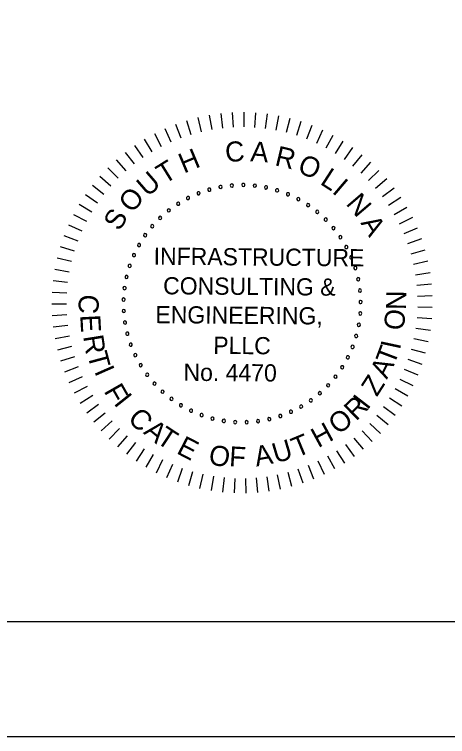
# Model space of a CAD drawing. Extents: x -146.3 to -98.2, y -113.4 to -84.1.
# Drawn here: x -112.521 to -110.009, y -113.391 to -109.207 of the extents above; entities that cross this region are included whole.
import ezdxf

# ---------------------------------------------------------------- set-up
doc = ezdxf.new("R2010")
doc.units = 0
for name, color, linetype in [('BR_BORDER LINES', 7, 'Continuous'), ('BR_TEXT', 7, 'Continuous'), ('Level 31', 7, 'Continuous')]:
    doc.layers.add(name, color=color, linetype=linetype)

msp = doc.modelspace()

# ---------------------------------------------------------------- linework, layer by layer
at = {"layer": 'BR_BORDER LINES'}
msp.add_line((-143.8657, -112.7249), (-98.9787, -112.7249), dxfattribs=at)
at = {"layer": 'BR_TEXT'}
for p, q in [((-111.4572, -109.8039), (-111.4373, -109.8864)), ((-111.3912, -109.7902), (-111.3765, -109.8738)), ((-111.3246, -109.7806), (-111.315, -109.865)), ((-111.2575, -109.7751), (-111.2531, -109.8599)), ((-111.1902, -109.7737), (-111.1909, -109.8586)), ((-111.123, -109.7764), (-111.1289, -109.8611)), ((-111.056, -109.7832), (-111.067, -109.8674)), ((-110.9896, -109.794), (-111.0057, -109.8774)), ((-111.5859, -109.8431), (-111.5562, -109.9226)), ((-111.5221, -109.8215), (-111.4973, -109.9027)), ((-110.9239, -109.8089), (-110.9451, -109.8911)), ((-110.8593, -109.8278), (-110.8855, -109.9085)), ((-111.6482, -109.8685), (-111.6137, -109.946)), ((-110.796, -109.8505), (-110.827, -109.9296)), ((-110.7341, -109.8771), (-110.7699, -109.9541)), ((-111.7089, -109.8976), (-111.6697, -109.9729)), ((-110.674, -109.9074), (-110.7145, -109.9821)), ((-111.8243, -109.9667), (-111.7763, -110.0367)), ((-111.7677, -109.9304), (-111.724, -110.0032)), ((-110.6159, -109.9413), (-110.6608, -110.0134)), ((-111.8787, -110.0065), (-111.8264, -110.0734)), ((-110.5599, -109.9787), (-110.6091, -110.0479)), ((-111.9305, -110.0494), (-111.8743, -110.113)), ((-110.5063, -110.0195), (-110.5597, -110.0855)), ((-111.9796, -110.0954), (-111.9196, -110.1555)), ((-110.4553, -110.0634), (-110.5126, -110.1261)), ((-110.4071, -110.1103), (-110.4681, -110.1694)), ((-112.0258, -110.1444), (-111.9623, -110.2007)), ((-110.3618, -110.1602), (-110.4263, -110.2154)), ((-112.069, -110.196), (-112.0021, -110.2484)), ((-110.3197, -110.2126), (-110.3874, -110.2638)), ((-112.1089, -110.2502), (-112.039, -110.2984)), ((-110.2808, -110.2676), (-110.3515, -110.3146)), ((-112.1454, -110.3068), (-112.0727, -110.3506)), ((-110.2454, -110.3248), (-110.3188, -110.3674)), ((-112.1784, -110.3654), (-112.1032, -110.4047)), ((-110.2134, -110.3841), (-110.2893, -110.4221)), ((-112.2078, -110.426), (-112.1303, -110.4606)), ((-110.1852, -110.4452), (-110.2633, -110.4785)), ((-112.2334, -110.4882), (-112.154, -110.5181)), ((-110.1608, -110.5079), (-110.2407, -110.5364)), ((-112.2552, -110.5519), (-112.1741, -110.5768)), ((-110.1402, -110.572), (-110.2217, -110.5955)), ((-112.2731, -110.6168), (-112.1906, -110.6367)), ((-110.1235, -110.6372), (-110.2064, -110.6557)), ((-112.287, -110.6827), (-112.2034, -110.6975)), ((-110.1109, -110.7033), (-110.1947, -110.7168)), ((-112.2968, -110.7493), (-112.2125, -110.759)), ((-110.1023, -110.7701), (-110.1868, -110.7784)), ((-112.3026, -110.8163), (-112.2178, -110.8209)), ((-110.0978, -110.8372), (-110.1827, -110.8404)), ((-112.3043, -110.8836), (-112.2194, -110.883)), ((-110.0975, -110.9045), (-110.1823, -110.9025)), ((-112.3018, -110.9509), (-112.2171, -110.9451)), ((-110.1012, -110.9717), (-110.1858, -110.9646)), ((-112.2953, -111.0179), (-112.2111, -111.0069)), ((-110.109, -111.0386), (-110.193, -111.0263)), ((-112.2847, -111.0843), (-112.2013, -111.0683)), ((-110.1208, -111.1048), (-110.2039, -111.0874)), ((-112.27, -111.15), (-112.1878, -111.1289)), ((-110.1367, -111.1703), (-110.2186, -111.1478)), ((-112.2514, -111.2147), (-112.1706, -111.1887)), ((-110.1566, -111.2346), (-110.2369, -111.2072)), ((-112.2289, -111.2781), (-112.1498, -111.2472)), ((-110.1803, -111.2976), (-110.2588, -111.2653)), ((-112.2025, -111.3401), (-112.1255, -111.3044)), ((-110.2078, -111.359), (-110.2842, -111.322)), ((-112.1725, -111.4003), (-112.0978, -111.36)), ((-110.239, -111.4186), (-110.3131, -111.3771)), ((-112.1388, -111.4586), (-112.0667, -111.4138)), ((-110.2738, -111.4762), (-110.3452, -111.4303)), ((-112.1016, -111.5147), (-112.0323, -111.4656)), ((-112.061, -111.5684), (-111.9949, -111.5152)), ((-110.3121, -111.5316), (-110.3805, -111.4814)), ((-110.3536, -111.5846), (-110.4188, -111.5303)), ((-112.0173, -111.6196), (-111.9546, -111.5624)), ((-110.3983, -111.6349), (-110.4601, -111.5767)), ((-111.9705, -111.668), (-111.9114, -111.6071)), ((-110.446, -111.6824), (-110.5041, -111.6206)), ((-111.9209, -111.7134), (-111.8656, -111.649)), ((-110.4965, -111.7269), (-110.5507, -111.6616)), ((-111.8686, -111.7558), (-111.8173, -111.6881)), ((-111.8138, -111.7949), (-111.7667, -111.7242)), ((-110.5496, -111.7683), (-110.5998, -111.6998)), ((-111.7567, -111.8305), (-111.714, -111.7571)), ((-110.6629, -111.8409), (-110.7043, -111.7668)), ((-110.6051, -111.8063), (-110.651, -111.7349)), ((-111.6975, -111.8627), (-111.6594, -111.7868)), ((-110.7226, -111.8719), (-110.7595, -111.7954)), ((-111.6365, -111.8911), (-111.6031, -111.8131)), ((-111.5739, -111.9158), (-111.5453, -111.8359)), ((-110.8472, -111.9227), (-110.8745, -111.8423)), ((-110.7842, -111.8992), (-110.8163, -111.8206)), ((-111.5099, -111.9366), (-111.4862, -111.8551)), ((-111.4447, -111.9535), (-111.4261, -111.8707)), ((-111.3787, -111.9664), (-111.3651, -111.8826)), ((-111.312, -111.9752), (-111.3035, -111.8907)), ((-111.2448, -111.9799), (-111.2415, -111.8951)), ((-111.1775, -111.9806), (-111.1794, -111.8957)), ((-111.1103, -111.9771), (-111.1173, -111.8925)), ((-111.0434, -111.9695), (-111.0556, -111.8855)), ((-110.9771, -111.9579), (-110.9944, -111.8748)), ((-110.9116, -111.9423), (-110.934, -111.8604))]:
    msp.add_line(p, q, dxfattribs=at)
for centre, start, end in [((-111.3904, -110.2219), 16.1422, 196.1422), ((-111.3904, -110.2219), 196.1422, 16.1422), ((-111.3257, -110.2067), 10.6038, 190.6038), ((-111.3257, -110.2067), 190.6038, 10.6038), ((-111.2599, -110.1978), 5.0653, 185.0653), ((-111.2599, -110.1978), 185.0653, 5.0653), ((-111.1935, -110.1952), 359.5268, 179.5268), ((-111.1935, -110.1952), 179.5268, 359.5268), ((-111.1272, -110.1991), 353.9884, 173.9884), ((-111.1272, -110.1991), 173.9884, 353.9884), ((-111.0615, -110.2094), 168.4499, 348.4499), ((-111.0615, -110.2094), 348.4499, 168.4499), ((-110.9972, -110.226), 342.9114, 162.9114), ((-111.5138, -110.2707), 27.2191, 207.2191), ((-111.4533, -110.2433), 21.6807, 201.6807), ((-111.4533, -110.2433), 201.6807, 21.6807), ((-110.9972, -110.226), 162.9114, 342.9114), ((-110.9347, -110.2486), 157.373, 337.373), ((-110.9347, -110.2486), 337.373, 157.373), ((-111.5714, -110.3038), 32.7576, 212.7576), ((-111.5714, -110.3038), 212.7576, 32.7576), ((-111.5138, -110.2707), 207.2191, 27.2191), ((-110.8748, -110.2773), 151.8345, 331.8345), ((-110.8748, -110.2773), 331.8345, 151.8345), ((-110.8178, -110.3115), 146.2961, 326.2961), ((-110.8178, -110.3115), 326.2961, 146.2961), ((-111.6256, -110.3423), 38.2961, 218.2961), ((-111.6256, -110.3423), 218.2961, 38.2961), ((-110.7645, -110.3511), 140.7576, 320.7576), ((-110.7645, -110.3511), 320.7576, 140.7576), ((-111.6757, -110.3859), 43.8345, 223.8345), ((-111.6757, -110.3859), 223.8345, 43.8345), ((-110.7152, -110.3957), 135.2191, 315.2191), ((-110.7152, -110.3957), 315.2191, 135.2191), ((-111.7215, -110.434), 49.373, 229.373), ((-111.7215, -110.434), 229.373, 49.373), ((-110.6705, -110.4448), 129.6807, 309.6807), ((-110.6705, -110.4448), 309.6807, 129.6807), ((-111.7624, -110.4864), 54.9114, 234.9114), ((-111.7624, -110.4864), 234.9114, 54.9114), ((-110.6307, -110.498), 124.1422, 304.1422), ((-110.6307, -110.498), 304.1422, 124.1422), ((-111.798, -110.5425), 60.4499, 240.4499), ((-111.798, -110.5425), 240.4499, 60.4499), ((-110.5962, -110.5548), 118.6038, 298.6038), ((-110.5962, -110.5548), 298.6038, 118.6038), ((-111.8281, -110.6017), 65.9884, 245.9884), ((-111.8281, -110.6017), 245.9884, 65.9884), ((-110.5674, -110.6147), 113.0653, 293.0653), ((-110.5674, -110.6147), 293.0653, 113.0653), ((-111.8522, -110.6636), 71.5268, 251.5268), ((-111.8522, -110.6636), 251.5268, 71.5268), ((-110.5444, -110.677), 107.5268, 287.5268), ((-110.5444, -110.677), 287.5268, 107.5268), ((-111.8704, -110.7275), 77.0653, 257.0653), ((-111.8704, -110.7275), 257.0653, 77.0653), ((-110.5277, -110.7413), 101.9884, 281.9884), ((-110.5277, -110.7413), 281.9884, 101.9884), ((-111.8822, -110.7929), 82.6038, 262.6038), ((-111.8822, -110.7929), 262.6038, 82.6038), ((-110.5171, -110.8069), 96.4499, 276.4499), ((-110.5171, -110.8069), 276.4499, 96.4499), ((-111.8877, -110.8591), 88.1422, 268.1422), ((-111.8877, -110.8591), 268.1422, 88.1422), ((-110.513, -110.8732), 90.9114, 270.9114), ((-110.513, -110.8732), 270.9114, 90.9114), ((-111.8868, -110.9256), 93.6807, 273.6807), ((-111.8868, -110.9256), 273.6807, 93.6807), ((-110.5153, -110.9396), 85.373, 265.373), ((-110.5153, -110.9396), 265.373, 85.373), ((-111.8794, -110.9916), 99.2191, 279.2191), ((-111.8794, -110.9916), 279.2191, 99.2191), ((-110.524, -111.0055), 79.8345, 259.8345), ((-110.524, -111.0055), 259.8345, 79.8345), ((-111.8658, -111.0566), 104.7576, 284.7576), ((-111.8658, -111.0566), 284.7576, 104.7576), ((-110.539, -111.0702), 74.2961, 254.2961), ((-110.539, -111.0702), 254.2961, 74.2961), ((-111.8459, -111.12), 110.2961, 290.2961), ((-111.8459, -111.12), 290.2961, 110.2961), ((-110.5601, -111.1332), 68.7576, 248.7576), ((-110.5601, -111.1332), 248.7576, 68.7576), ((-111.82, -111.1812), 115.8345, 295.8345), ((-111.82, -111.1812), 295.8345, 115.8345), ((-110.5873, -111.1938), 63.2191, 243.2191), ((-110.5873, -111.1938), 243.2191, 63.2191), ((-111.7883, -111.2396), 121.373, 301.373), ((-111.7883, -111.2396), 301.373, 121.373), ((-110.6202, -111.2515), 57.6807, 237.6807), ((-110.6202, -111.2515), 237.6807, 57.6807), ((-111.7511, -111.2946), 126.9114, 306.9114), ((-111.7511, -111.2946), 306.9114, 126.9114), ((-110.6585, -111.3058), 52.1422, 232.1422), ((-110.6585, -111.3058), 232.1422, 52.1422), ((-111.7088, -111.3459), 132.4499, 312.4499), ((-111.7088, -111.3459), 312.4499, 132.4499), ((-110.7018, -111.3562), 46.6038, 226.6038), ((-110.7018, -111.3562), 226.6038, 46.6038), ((-111.6617, -111.3927), 137.9884, 317.9884), ((-111.6617, -111.3927), 317.9884, 137.9884), ((-110.7499, -111.4021), 41.0653, 221.0653), ((-111.6104, -111.4349), 143.5268, 323.5268), ((-111.6104, -111.4349), 323.5268, 143.5268), ((-110.8021, -111.4432), 35.5268, 215.5268), ((-110.7499, -111.4021), 221.0653, 41.0653), ((-111.5552, -111.4719), 149.0653, 329.0653), ((-111.5552, -111.4719), 329.0653, 149.0653), ((-110.858, -111.479), 29.9884, 209.9884), ((-110.858, -111.479), 209.9884, 29.9884), ((-110.8021, -111.4432), 215.5268, 35.5268), ((-111.4966, -111.5033), 154.6038, 334.6038), ((-111.4966, -111.5033), 334.6038, 154.6038), ((-111.4354, -111.529), 340.1422, 160.1422), ((-110.9172, -111.5093), 24.4499, 204.4499), ((-110.9172, -111.5093), 204.4499, 24.4499), ((-111.4354, -111.529), 160.1422, 340.1422), ((-111.3719, -111.5487), 165.6807, 345.6807), ((-111.3719, -111.5487), 345.6807, 165.6807), ((-111.3068, -111.5621), 171.2191, 351.2191), ((-111.3068, -111.5621), 351.2191, 171.2191), ((-111.2408, -111.5692), 356.7576, 176.7576), ((-111.1743, -111.5699), 2.2961, 182.2961), ((-111.1081, -111.5641), 7.8345, 187.8345), ((-111.0428, -111.552), 13.373, 193.373), ((-111.0428, -111.552), 193.373, 13.373), ((-110.979, -111.5337), 18.9114, 198.9114), ((-110.979, -111.5337), 198.9114, 18.9114), ((-111.2408, -111.5692), 176.7576, 356.7576), ((-111.1743, -111.5699), 182.2961, 2.2961), ((-111.1081, -111.5641), 187.8345, 7.8345)]:
    msp.add_arc(centre, 0.00935, start, end, dxfattribs=at)
at = {"layer": 'Level 31'}
msp.add_lwpolyline([(-146.31, -113.3914), (-98.3112, -113.3914), (-98.3112, -84.0588), (-146.31, -84.0588)], close=True, dxfattribs=at)

# ---------------------------------------------------------------- texts
at = {"layer": 'BR_TEXT'}
for s, height, rotation, p in [('C', 0.1163, 4.7281, (-111.2942, -110.0638)), ('A', 0.1163, 355.6981, (-111.1549, -110.0572)), ('R', 0.1163, 346.6681, (-111.0158, -110.0799)), ('H', 0.1163, 22.7882, (-111.5379, -110.1297)), ('T', 0.1163, 31.8182, (-111.651, -110.1932)), ('O', 0.1163, 337.638, (-110.8855, -110.1196)), ('L', 0.1163, 327.108, (-110.7537, -110.1869)), ('U', 0.1163, 40.8482, (-111.7488, -110.268)), ('I', 0.1163, 319.578, (-110.6837, -110.2373)), ('O', 0.1163, 49.8782, (-111.8381, -110.3627)), ('N', 0.1163, 310.548, (-110.6026, -110.305)), ('S', 0.1163, 58.9083, (-111.912, -110.467)), ('A', 0.1163, 301.5179, (-110.5158, -110.4149)), ('INFRASTRUCTURE', 0.099693, 359.5268, (-111.7138, -110.657)), ('CONSULTING &', 0.099693, 359.5268, (-111.6588, -110.8285)), ('C', 0.1163, 267.025, (-112.1453, -110.8269)), ('N', 0.1163, 89.2085, (-110.2501, -110.9199)), ('ENGINEERING,', 0.099693, 359.5268, (-111.7036, -110.9957)), ('O', 0.1163, 83.2085, (-110.2649, -111.0418)), ('E', 0.1163, 273.025, (-112.1394, -110.949)), ('R', 0.1163, 279.025, (-112.1224, -111.072)), ('PLLC', 0.09969, 359.5268, (-111.368, -111.1738)), ('T', 0.1163, 69.3954, (-110.3198, -111.2442)), ('I', 0.1163, 77.9093, (-110.2856, -111.1542)), ('T', 0.1163, 285.025, (-112.0992, -111.177)), ('A', 0.1163, 63.3954, (-110.3609, -111.3246)), ('I', 0.1163, 293.7713, (-112.0596, -111.2745)), ('No. 4470', 0.09969, 359.5268, (-111.5407, -111.3297)), ('Z', 0.1163, 57.3954, (-110.4193, -111.4264)), ('F', 0.1163, 299.7713, (-112.0047, -111.3892)), ('I', 0.1163, 308.5268, (-111.9486, -111.461)), ('R', 0.1163, 44.5268, (-110.5399, -111.5664)), ('I', 0.1163, 52.3339, (-110.4741, -111.5033)), ('C', 0.1163, 314.5268, (-111.8694, -111.5545)), ('O', 0.1163, 38.5268, (-110.642, -111.6463)), ('A', 0.1163, 320.5268, (-111.7772, -111.6326)), ('T', 0.1163, 326.5268, (-111.7046, -111.6839)), ('H', 0.1163, 28.5268, (-110.7595, -111.721)), ('T', 0.1163, 22.5268, (-110.8837, -111.7767)), ('E', 0.1163, 332.5268, (-111.5865, -111.7477)), ('U', 0.1163, 16.5268, (-111.006, -111.8092)), ('O', 0.1163, 350.5268, (-111.3997, -111.8128)), ('F', 0.1163, 356.5268, (-111.2778, -111.825)), ('A', 0.1163, 10.5268, (-111.1179, -111.8272))]:
    msp.add_text(s, height=height, rotation=rotation, dxfattribs=at).set_placement(p)

doc.saveas('drawing.dxf')
